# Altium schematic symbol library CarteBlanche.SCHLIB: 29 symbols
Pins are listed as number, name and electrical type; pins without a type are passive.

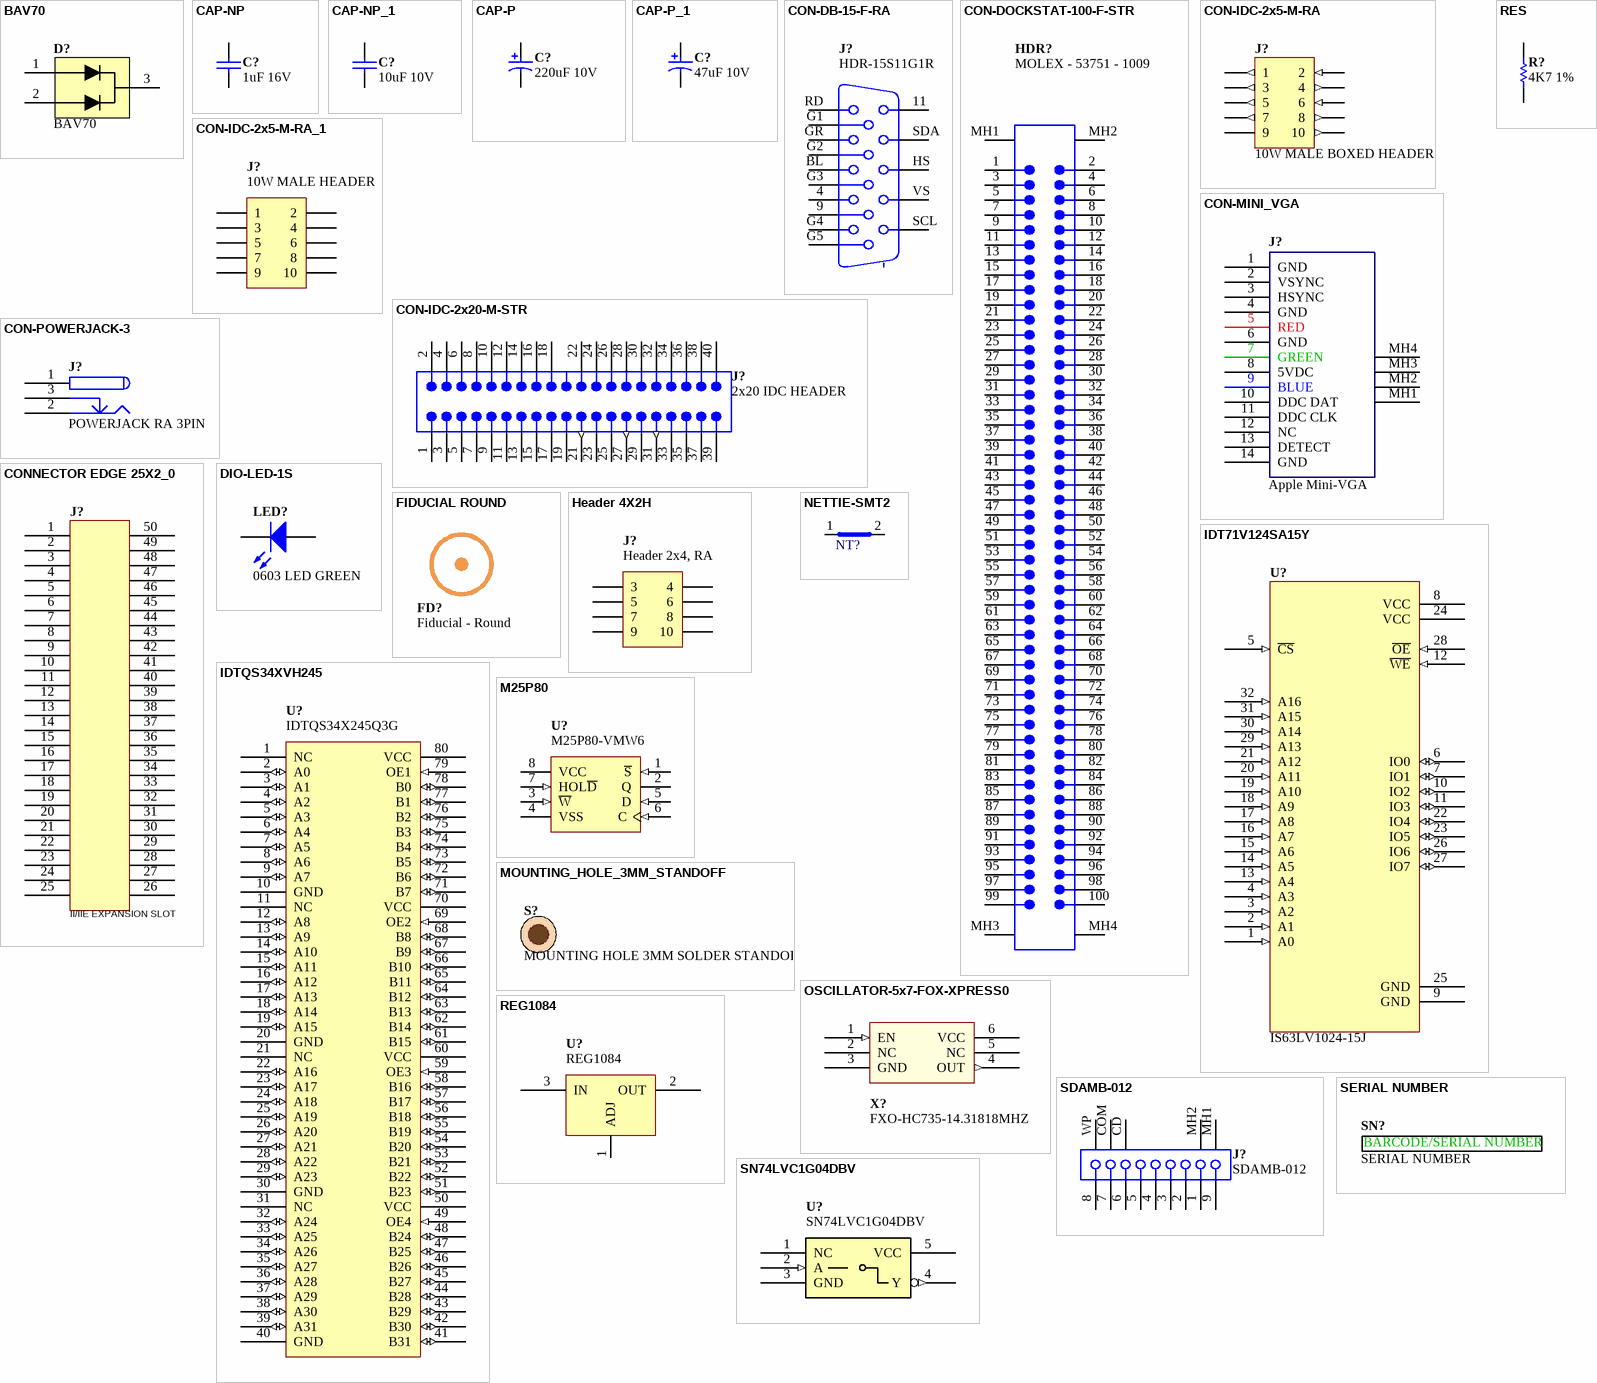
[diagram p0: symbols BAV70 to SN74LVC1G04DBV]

## BAV70
designator D?
BAV70, SOT-23 Shottky Diode Pair Common Cathode
footprint SOT95P230-3
pins: 1, 2, 3
2 alternate drawings of the same symbol

## CAP-NP
designator C?, comment 1uF 16V
Capacitor, Ceramic, 1uF 10% 16V 0402 (1005) X7R
footprint CAPC1005-STAR
pins: 1, 2

## CAP-NP_1
designator C?, comment 10uF 10V
Capacitor, Ceramic, 1uF 10% 16V 0402 (1005) X7R
footprint CAPC1005-STAR
footprint CAPC2012-STAR
pins: 1, 2

## CAP-P
designator C?, comment 220uF 10V
Capacitor, Tantalum, 220uF 10% 10V MCCT-D (7343-31)
footprint CAPC7343-STAR
pins: 1, 2

## CAP-P_1
designator C?, comment 47uF 10V
Capacitor, Tantalum, 220uF 10% 10V MCCT-D (7343-31)
footprint CAPC7343-STAR
footprint CAPC3528-STAR
pins: 1, 2

## CON-DB-15-F-RA
designator J?, comment HDR-15S11G1R
Socket, High-Density DB15 (HD15) Female Through-hole
footprint DB15-VGA-Female
pins: 4 "Monitor ID Bit 2 (Ground)", 9 "Key (not used)", 11 (power) "Monitor ID Bit 0 (Ground)", BL "Blue Video", G1 (power) "Red Return (Ground)", G2 (power) "Green Return (Ground)", G3 (power) "Blue Return (Ground)", G4 (power) "Ground", G5 (power) "Sync Return (Ground)", GR "Green Video", HS "Horizontal Zync", RD "Red Video", SCL "Vertical Sync", SDA "Monitor ID Bit 1 (Not Used)", VS "Vertical Sync"

## CON-DOCKSTAT-100-F-STR
designator HDR?, comment MOLEX - 53751 - 1009
Connector, MOLEX - 53751 - 1009
footprint 53751
pins: 1, 2, 3, 4, 5, 6, 7, 8, 9, 10, 11, 12, 13, 14, 15, 16, 17, 18, 19, 20, 21, 22, 23, 24, 25, 26, 27, 28, 29, 30, 31, 32, 33, 34, 35, 36, 37, 38, 39, 40, 41, 42, 43, 44, 45, 46, 47, 48, 49, 50, 51, 52, 53, 54, 55, 56, 57, 58, 59, 60, 61, 62, 63, 64, 65, 66, 67, 68, 69, 70, 71, 72, 73, 74, 75, 76, 77, 78, 79, 80, 81, 82, 83, 84, 85, 86, 87, 88, 89, 90, 91, 92, 93, 94, 95, 96, 97, 98, 99, 100, MH1, MH2, MH3, MH4
1 alternate drawing of the same symbol

## CON-IDC-2x5-M-RA
designator J?, comment 10W MALE BOXED HEADER
Header IDC, 2x5 Pin Right-Angle 2.54mm Pitch (Boxed-Male)
footprint 918510X323 (Connector; IDC, Low Profile Male Header, Thru-Hole; 10 Position; Right Angle; Pitch 2.54 mm; Body 20.32 x 8.9 x 9.2 mm (LxWxH))
pins: 1 (out), 2 (in), 3 (out), 4 (out), 5 (out), 6 (in), 7 (out), 8 (out), 9, 10 (out)

## CON-IDC-2x5-M-RA_1
designator J?, comment 10W MALE HEADER
Header IDC, 2x5 Pin Right-Angle 2.54mm Pitch (Boxed-Male)
footprint 918510X323 (Connector; IDC, Low Profile Male Header, Thru-Hole; 10 Position; Right Angle; Pitch 2.54 mm; Body 20.32 x 8.9 x 9.2 mm (LxWxH))
pins: 1, 2, 3, 4, 5, 6, 7, 8, 9, 10

## CON-IDC-2x20-M-STR
designator J?, comment 2x20 IDC HEADER
Header, Boxed 2x20 Pin Vertical 2.54mm Pitch
footprint 918540x324
pins: 1, 2, 3, 4, 5, 6, 7, 8, 9, 10, 11, 12, 13, 14, 15, 16, 17, 18, 19, 21 (out), 22, 23, 24, 25, 26, 27 (out), 28, 29, 30, 31 (out), 32, 33, 34, 35, 36, 37, 38, 39, 40

## CON-MINI_VGA
designator J?, comment Apple Mini-VGA  (no BOM)
Socket, VGA/RGB Connector, 1.00mm Pitch, Through-hole, Suyin
footprint CON_MINI_VGA
pins: 1 GND, 2 VSYNC, 3 HSYNC, 4 GND, 5 RED, 6 GND, 7 GREEN, 8 5VDC, 9 BLUE, 10 DDC DAT, 11 DDC CLK, 12 NC, 13 DETECT, 14 GND, MH1, MH2, MH3, MH4

## CON-POWERJACK-3
designator J?, comment POWERJACK RA 3PIN
Connector, RA 3 Conductor Power Jack
footprint KLD-0202
pins: 1 (power), 2 (power), 3 (power)

## CONNECTOR EDGE 25X2_0
designator J?, comment II/IIE EXPANSION SLOT  (no BOM)
footprint APPLE II EDGE CONNECTOR (Footprint not found)
pins: 1, 2, 3, 4, 5, 6, 7, 8, 9, 10, 11, 12, 13, 14, 15, 16, 17, 18, 19, 20, 21, 22, 23, 24, 25, 26, 27, 28, 29, 30, 31, 32, 33, 34, 35, 36, 37, 38, 39, 40, 41, 42, 43, 44, 45, 46, 47, 48, 49, 50

## DIO-LED-1S
designator LED?, comment 0603 LED GREEN
LED, SMD Green 0603 (1608) 60mCd
footprint 0603LED_Kingbright_Green
pins: 1 A, 2 K

## FIDUCIAL ROUND
designator FD?, comment Fiducial - Round
Fiducial - Round 1.5mm Top-Bottom
footprint FIDUCIAL ROUND

## Header 4X2H
designator J?, comment Header 2x4, RA
Header, Right Angle, 8-Pin, Dual row
footprint HDR2X4H (Connector; Header; 4x2 Position; Right Angle)
pins: 3, 4, 5, 6, 7, 8, 9, 10

## IDT71V124SA15Y
designator U?, comment IS63LV1024-15J
IC SRAM 128Kx8 15nS ASYNC 32-SOJ
footprint SO-J32
pins: 1 A0 (in) "Address 0", 2 A1 (in) "Address 1", 3 A2 (in) "Address 3", 4 A3 (in) "Address 3", 5 ~{CS} (in) "Chip Select", 6 IO0 (io) "Data 0", 7 IO1 (io) "Data 1", 8 VCC (power) "Pos Supply", 9 GND (power), 10 IO2 (io) "Data 2", 11 IO3 (io) "Data 3", 12 ~{WE} (in) "Write Enable", 13 A4 (in) "Address 4", 14 A5 (in) "Address 5", 15 A6 (in) "Address 6", 16 A7 (in) "Address 7", 17 A8 (in) "Address 8", 18 A9 (in) "Address 9", 19 A10 (in) "Address 10", 20 A11 (in) "Address 11", 21 A12 (in) "Address 12", 22 IO4 (io) "Data 4", 23 IO5 (io) "Data 5", 24 VCC (power) "Pos Supply", 25 GND (power), 26 IO6 (io) "Data 6", 27 IO7 (io) "Data 7", 28 ~{OE} (in) "Output Enable", 29 A13 (in) "Address 13", 30 A14 (in) "Address 14", 31 A15 (in) "Address 15", 32 A16 (in) "Address 16"

## IDTQS34XVH245
designator U?, comment IDTQS34X245Q3G
IC BUS SWITCH 32BIT CMOS 80QVSOP
footprint QVSOP80 (Footprint not found)
pins: 1 NC "Analog Input 0", 2 A0 (io) "Analog Input 0", 3 A1 (io) "Analog Input 0", 4 A2 (io) "Analog Input 3/ Reference Input", 5 A3 (io) "I2C Clock Line", 6 A4 (io) "I2C Data Line", 7 A5 (io) "GND", 8 A6 (io), 9 A7 (io), 10 GND (power), 11 NC, 12 A8 (io), 13 A9 (io), 14 A10 (io), 15 A11 (io), 16 A12 (io), 17 A13 (io), 18 A14 (io), 19 A15 (io), 20 GND (power), 21 NC, 22 A16 (io), 23 A17 (io), 24 A18 (io), 25 A19 (io), 26 A20 (io), 27 A21 (io), 28 A22 (io), 29 A23 (io), 30 GND (power), 31 NC, 32 A24 (io), 33 A25 (io), 34 A26 (io), 35 A27 (io), 36 A28 (io), 37 A29 (io), 38 A30 (io), 39 A31 (io), 40 GND (power), 41 B31 (io), 42 B30 (io), 43 B29 (io), 44 B28 (io), 45 B27 (io), 46 B26 (io), 47 B25 (io), 48 B24 (io), 49 OE4 (in), 50 VCC (power), 51 B23 (io), 52 B22 (io), 53 B21 (io), 54 B20 (io), 55 B19 (io), 56 B18 (io), 57 B17 (io), 58 B16 (io), 59 OE3 (in), 60 VCC (power), 61 B15 (io), 62 B14 (io), 63 B13 (io), 64 B12 (io), 65 B11 (io), 66 B10 (io), 67 B9 (io), 68 B8 (io), 69 OE2 (in), 70 VCC (power), 71 B7 (io), 72 B6 (io), 73 B5 (io), 74 B4 (io), 75 B3 (io), 76 B2 (io), 77 B1 (io), 78 B0 (io), 79 OE1 (in), 80 VCC (power)

## M25P80
designator U?, comment M25P80-VMW6
IC SERIAL FLASH 8MBIT 3V 8-SOIC WIDE
footprint SOIC8-200-BODY
pins: 1 ~{S} (in), 2 Q (hiz) "Serial Output", 3 ~{W} (in) "Serial Output", 4 VSS (power) "Serial Output", 5 D (in) "Serial Input", 6 C (in) "Serial Input", 7 HOL~{D} (in) "Serial Input", 8 VCC (power) "Serial Input"

## MOUNTING_HOLE_3MM_STANDOFF
designator S?, comment MOUNTING HOLE 3MM SOLDER STANDOFF
Solder Standoff, M3 Screw, Gold Plated, Round Pad
footprint STANDOFF_SOLDER_3MM
pins: 1 hidden

## NETTIE-SMT2
designator NT?, comment Net Tie SMT2  (value not drawn)  (net tie, no BOM)
Net-Tie, Surface Mount, 2 x 0.4mm x 0.2mm SMT Pads - For 0.2mm Track
footprint NETTIE-SMT2-31X51 (Footprint not found)
pins: 1 Net1, 2 Net2

## OSCILLATOR-5x7-FOX-XPRESS0
designator X?, comment FXO-HC735-14.31818MHZ
OSCILLATOR 14.31818 MHZ 3.3V SMD
footprint OSCILLATOR-5x7-FOX-XPRESS0
pins: 1 EN (in), 2 NC, 3 GND (power), 4 OUT (out), 5 NC, 6 VCC (power)

## REG1084
designator U?
IC REG POSITIVE 5A LDO TO-263
footprint TO-263
pins: 1 ADJ, 2 OUT, 3 IN

## RES
designator R?, comment 4K7 1%
Resistor, 4K7 1% 0402 (1005)
footprint RESC1005-STAR
pins: 1, 2

## SDAMB-012
designator J?
KINGFONT SDCARD Connector SDAMB-012
footprint SDAMB-012
pins: 1 "CD/DAT3", 2 "CMD/D1", 3 "VSS1", 4 "VDD", 5 "CLK/SCLK", 6 "VSS2", 7 "DAT0", 8 "DAT1", 9 "DAT3", CD "Card Detect Indication", COM, MH1 "Tab", MH2 "Tab", WP "Write Protect"

## SERIAL NUMBER
designator SN?  (no BOM)
footprint SERIAL_NO2 (Footprint not found)

## SN74LVC1G04DBV
designator U?
IC SINGLE INVERTER-GATE SOT-23-5
footprint SOT95P280-5
pins: 1 NC, 2 A (in), 3 GND (power), 4 Y (out), 5 VCC (power)

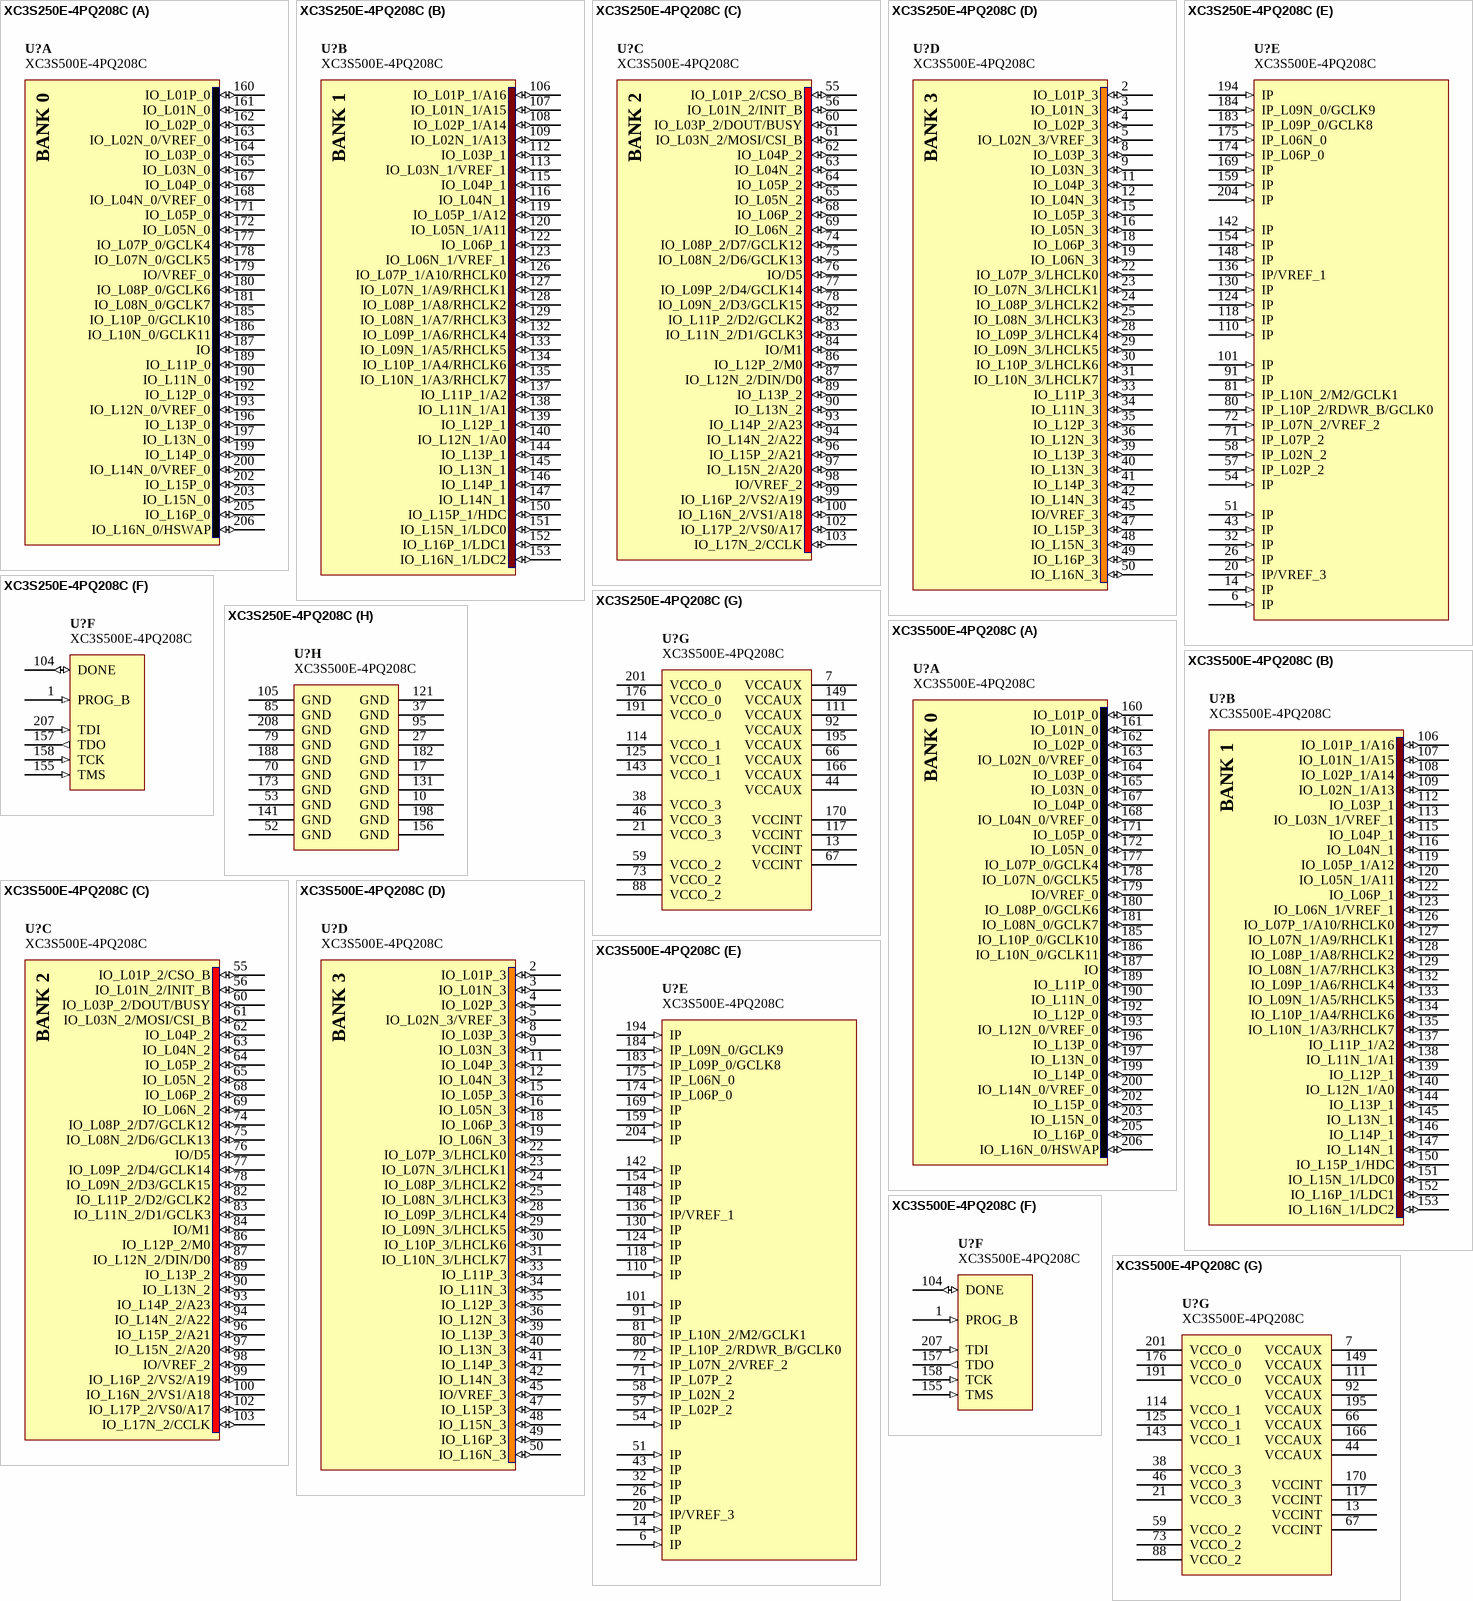
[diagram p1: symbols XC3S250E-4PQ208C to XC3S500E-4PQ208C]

## XC3S250E-4PQ208C
designator U?, comment XC3S500E-4PQ208C
IC SPARTAN-3E FPGA 500K 208-PQFP; EnablePinSwap: True
footprint PQ208_N (Shrink QFP, 208-Leads, Body 28x28mm, Pitch 0.5mm, IPC Medium Density)
footprint PQ208_L (Shrink QFP, 208-Leads, Body 28x28mm, Pitch 0.5mm, IPC High Density)
footprint PQ208_M (Shrink QFP, 208-Leads, Body 28x28mm, Pitch 0.5mm, IPC Low Density)
3D model XC3S250E-PQ208 (208-Pin Plastic Quad Flat Pack (PQ208))
signal-integrity model XC3S250E_PQ208 (Spartan-3E)
part A pins: 160 IO_L01P_0 (io), 161 IO_L01N_0 (io), 162 IO_L02P_0 (io), 163 IO_L02N_0/VREF_0 (io), 164 IO_L03P_0 (io), 165 IO_L03N_0 (io), 167 IO_L04P_0 (io), 168 IO_L04N_0/VREF_0 (io), 171 IO_L05P_0 (io), 172 IO_L05N_0 (io), 177 IO_L07P_0/GCLK4 (io), 178 IO_L07N_0/GCLK5 (io), 179 IO/VREF_0 (io), 180 IO_L08P_0/GCLK6 (io), 181 IO_L08N_0/GCLK7 (io), 185 IO_L10P_0/GCLK10 (io), 186 IO_L10N_0/GCLK11 (io), 187 IO (io), 189 IO_L11P_0 (io), 190 IO_L11N_0 (io), 192 IO_L12P_0 (io), 193 IO_L12N_0/VREF_0 (io), 196 IO_L13P_0 (io), 197 IO_L13N_0 (io), 199 IO_L14P_0 (io), 200 IO_L14N_0/VREF_0 (io), 202 IO_L15P_0 (io), 203 IO_L15N_0 (io), 205 IO_L16P_0 (io), 206 IO_L16N_0/HSWAP (io)
part B pins: 106 IO_L01P_1/A16 (io), 107 IO_L01N_1/A15 (io), 108 IO_L02P_1/A14 (io), 109 IO_L02N_1/A13 (io), 112 IO_L03P_1 (io), 113 IO_L03N_1/VREF_1 (io), 115 IO_L04P_1 (io), 116 IO_L04N_1 (io), 119 IO_L05P_1/A12 (io), 120 IO_L05N_1/A11 (io), 122 IO_L06P_1 (io), 123 IO_L06N_1/VREF_1 (io), 126 IO_L07P_1/A10/RHCLK0 (io), 127 IO_L07N_1/A9/RHCLK1 (io), 128 IO_L08P_1/A8/RHCLK2 (io), 129 IO_L08N_1/A7/RHCLK3 (io), 132 IO_L09P_1/A6/RHCLK4 (io), 133 IO_L09N_1/A5/RHCLK5 (io), 134 IO_L10P_1/A4/RHCLK6 (io), 135 IO_L10N_1/A3/RHCLK7 (io), 137 IO_L11P_1/A2 (io), 138 IO_L11N_1/A1 (io), 139 IO_L12P_1 (io), 140 IO_L12N_1/A0 (io), 144 IO_L13P_1 (io), 145 IO_L13N_1 (io), 146 IO_L14P_1 (io), 147 IO_L14N_1 (io), 150 IO_L15P_1/HDC (io), 151 IO_L15N_1/LDC0 (io), 152 IO_L16P_1/LDC1 (io), 153 IO_L16N_1/LDC2 (io)
part C pins: 55 IO_L01P_2/CSO_B (io), 56 IO_L01N_2/INIT_B (io), 60 IO_L03P_2/DOUT/BUSY (io), 61 IO_L03N_2/MOSI/CSI_B (io), 62 IO_L04P_2 (io), 63 IO_L04N_2 (io), 64 IO_L05P_2 (io), 65 IO_L05N_2 (io), 68 IO_L06P_2 (io), 69 IO_L06N_2 (io), 74 IO_L08P_2/D7/GCLK12 (io), 75 IO_L08N_2/D6/GCLK13 (io), 76 IO/D5 (io), 77 IO_L09P_2/D4/GCLK14 (io), 78 IO_L09N_2/D3/GCLK15 (io), 82 IO_L11P_2/D2/GCLK2 (io), 83 IO_L11N_2/D1/GCLK3 (io), 84 IO/M1 (io), 86 IO_L12P_2/M0 (io), 87 IO_L12N_2/DIN/D0 (io), 89 IO_L13P_2 (io), 90 IO_L13N_2 (io), 93 IO_L14P_2/A23 (io), 94 IO_L14N_2/A22 (io), 96 IO_L15P_2/A21 (io), 97 IO_L15N_2/A20 (io), 98 IO/VREF_2 (io), 99 IO_L16P_2/VS2/A19 (io), 100 IO_L16N_2/VS1/A18 (io), 102 IO_L17P_2/VS0/A17 (io), 103 IO_L17N_2/CCLK (io)
part D pins: 2 IO_L01P_3 (io), 3 IO_L01N_3 (io), 4 IO_L02P_3 (io), 5 IO_L02N_3/VREF_3 (io), 8 IO_L03P_3 (io), 9 IO_L03N_3 (io), 11 IO_L04P_3 (io), 12 IO_L04N_3 (io), 15 IO_L05P_3 (io), 16 IO_L05N_3 (io), 18 IO_L06P_3 (io), 19 IO_L06N_3 (io), 22 IO_L07P_3/LHCLK0 (io), 23 IO_L07N_3/LHCLK1 (io), 24 IO_L08P_3/LHCLK2 (io), 25 IO_L08N_3/LHCLK3 (io), 28 IO_L09P_3/LHCLK4 (io), 29 IO_L09N_3/LHCLK5 (io), 30 IO_L10P_3/LHCLK6 (io), 31 IO_L10N_3/LHCLK7 (io), 33 IO_L11P_3 (io), 34 IO_L11N_3 (io), 35 IO_L12P_3 (io), 36 IO_L12N_3 (io), 39 IO_L13P_3 (io), 40 IO_L13N_3 (io), 41 IO_L14P_3 (io), 42 IO_L14N_3 (io), 45 IO/VREF_3 (io), 47 IO_L15P_3 (io), 48 IO_L15N_3 (io), 49 IO_L16P_3 (io), 50 IO_L16N_3 (io)
part E pins: 6 IP (in), 14 IP (in), 20 IP/VREF_3 (in), 26 IP (in), 32 IP (in), 43 IP (in), 51 IP (in), 54 IP (in), 57 IP_L02P_2 (in), 58 IP_L02N_2 (in), 71 IP_L07P_2 (in), 72 IP_L07N_2/VREF_2 (in), 80 IP_L10P_2/RDWR_B/GCLK0 (in), 81 IP_L10N_2/M2/GCLK1 (in), 91 IP (in), 101 IP (in), 110 IP (in), 118 IP (in), 124 IP (in), 130 IP (in), 136 IP/VREF_1 (in), 142 IP (in), 148 IP (in), 154 IP (in), 159 IP (in), 169 IP (in), 174 IP_L06P_0 (in), 175 IP_L06N_0 (in), 183 IP_L09P_0/GCLK8 (in), 184 IP_L09N_0/GCLK9 (in), 194 IP (in), 204 IP (in)
part F pins: 1 PROG_B (in), 104 DONE (io), 155 TMS (in), 157 TDO (out), 158 TCK (in), 207 TDI (in)
part G pins: 7 VCCAUX (power), 13 VCCINT (power), 21 VCCO_3 (power), 38 VCCO_3 (power), 44 VCCAUX (power), 46 VCCO_3 (power), 59 VCCO_2 (power), 66 VCCAUX (power), 67 VCCINT (power), 73 VCCO_2 (power), 88 VCCO_2 (power), 92 VCCAUX (power), 111 VCCAUX (power), 114 VCCO_1 (power), 117 VCCINT (power), 125 VCCO_1 (power), 143 VCCO_1 (power), 149 VCCAUX (power), 166 VCCAUX (power), 170 VCCINT (power), 176 VCCO_0 (power), 191 VCCO_0 (power), 195 VCCAUX (power), 201 VCCO_0 (power)
part H pins: 10 GND (power), 17 GND (power), 27 GND (power), 37 GND (power), 52 GND (power), 53 GND (power), 70 GND (power), 79 GND (power), 85 GND (power), 95 GND (power), 105 GND (power), 121 GND (power), 131 GND (power), 141 GND (power), 156 GND (power), 173 GND (power), 182 GND (power), 188 GND (power), 198 GND (power), 208 GND (power)

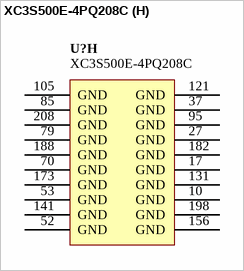
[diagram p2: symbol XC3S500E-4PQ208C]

## XC3S500E-4PQ208C
designator U?
IC SPARTAN-3E FPGA 500K 208-PQFP; EnablePinSwap: True
footprint PQ208_N (Shrink QFP, 208-Leads, Body 28x28mm, Pitch 0.5mm, IPC Medium Density)
footprint PQ208_L (Shrink QFP, 208-Leads, Body 28x28mm, Pitch 0.5mm, IPC High Density)
footprint PQ208_M (Shrink QFP, 208-Leads, Body 28x28mm, Pitch 0.5mm, IPC Low Density)
3D model XC3S500E-PQ208 (208-Pin Plastic Quad Flat Pack (PQ208))
signal-integrity model XC3S500E_PQ208 (Spartan-3E)
part A pins: 160 IO_L01P_0 (io), 161 IO_L01N_0 (io), 162 IO_L02P_0 (io), 163 IO_L02N_0/VREF_0 (io), 164 IO_L03P_0 (io), 165 IO_L03N_0 (io), 167 IO_L04P_0 (io), 168 IO_L04N_0/VREF_0 (io), 171 IO_L05P_0 (io), 172 IO_L05N_0 (io), 177 IO_L07P_0/GCLK4 (io), 178 IO_L07N_0/GCLK5 (io), 179 IO/VREF_0 (io), 180 IO_L08P_0/GCLK6 (io), 181 IO_L08N_0/GCLK7 (io), 185 IO_L10P_0/GCLK10 (io), 186 IO_L10N_0/GCLK11 (io), 187 IO (io), 189 IO_L11P_0 (io), 190 IO_L11N_0 (io), 192 IO_L12P_0 (io), 193 IO_L12N_0/VREF_0 (io), 196 IO_L13P_0 (io), 197 IO_L13N_0 (io), 199 IO_L14P_0 (io), 200 IO_L14N_0/VREF_0 (io), 202 IO_L15P_0 (io), 203 IO_L15N_0 (io), 205 IO_L16P_0 (io), 206 IO_L16N_0/HSWAP (io)
part B pins: 106 IO_L01P_1/A16 (io), 107 IO_L01N_1/A15 (io), 108 IO_L02P_1/A14 (io), 109 IO_L02N_1/A13 (io), 112 IO_L03P_1 (io), 113 IO_L03N_1/VREF_1 (io), 115 IO_L04P_1 (io), 116 IO_L04N_1 (io), 119 IO_L05P_1/A12 (io), 120 IO_L05N_1/A11 (io), 122 IO_L06P_1 (io), 123 IO_L06N_1/VREF_1 (io), 126 IO_L07P_1/A10/RHCLK0 (io), 127 IO_L07N_1/A9/RHCLK1 (io), 128 IO_L08P_1/A8/RHCLK2 (io), 129 IO_L08N_1/A7/RHCLK3 (io), 132 IO_L09P_1/A6/RHCLK4 (io), 133 IO_L09N_1/A5/RHCLK5 (io), 134 IO_L10P_1/A4/RHCLK6 (io), 135 IO_L10N_1/A3/RHCLK7 (io), 137 IO_L11P_1/A2 (io), 138 IO_L11N_1/A1 (io), 139 IO_L12P_1 (io), 140 IO_L12N_1/A0 (io), 144 IO_L13P_1 (io), 145 IO_L13N_1 (io), 146 IO_L14P_1 (io), 147 IO_L14N_1 (io), 150 IO_L15P_1/HDC (io), 151 IO_L15N_1/LDC0 (io), 152 IO_L16P_1/LDC1 (io), 153 IO_L16N_1/LDC2 (io)
part C pins: 55 IO_L01P_2/CSO_B (io), 56 IO_L01N_2/INIT_B (io), 60 IO_L03P_2/DOUT/BUSY (io), 61 IO_L03N_2/MOSI/CSI_B (io), 62 IO_L04P_2 (io), 63 IO_L04N_2 (io), 64 IO_L05P_2 (io), 65 IO_L05N_2 (io), 68 IO_L06P_2 (io), 69 IO_L06N_2 (io), 74 IO_L08P_2/D7/GCLK12 (io), 75 IO_L08N_2/D6/GCLK13 (io), 76 IO/D5 (io), 77 IO_L09P_2/D4/GCLK14 (io), 78 IO_L09N_2/D3/GCLK15 (io), 82 IO_L11P_2/D2/GCLK2 (io), 83 IO_L11N_2/D1/GCLK3 (io), 84 IO/M1 (io), 86 IO_L12P_2/M0 (io), 87 IO_L12N_2/DIN/D0 (io), 89 IO_L13P_2 (io), 90 IO_L13N_2 (io), 93 IO_L14P_2/A23 (io), 94 IO_L14N_2/A22 (io), 96 IO_L15P_2/A21 (io), 97 IO_L15N_2/A20 (io), 98 IO/VREF_2 (io), 99 IO_L16P_2/VS2/A19 (io), 100 IO_L16N_2/VS1/A18 (io), 102 IO_L17P_2/VS0/A17 (io), 103 IO_L17N_2/CCLK (io)
part D pins: 2 IO_L01P_3 (io), 3 IO_L01N_3 (io), 4 IO_L02P_3 (io), 5 IO_L02N_3/VREF_3 (io), 8 IO_L03P_3 (io), 9 IO_L03N_3 (io), 11 IO_L04P_3 (io), 12 IO_L04N_3 (io), 15 IO_L05P_3 (io), 16 IO_L05N_3 (io), 18 IO_L06P_3 (io), 19 IO_L06N_3 (io), 22 IO_L07P_3/LHCLK0 (io), 23 IO_L07N_3/LHCLK1 (io), 24 IO_L08P_3/LHCLK2 (io), 25 IO_L08N_3/LHCLK3 (io), 28 IO_L09P_3/LHCLK4 (io), 29 IO_L09N_3/LHCLK5 (io), 30 IO_L10P_3/LHCLK6 (io), 31 IO_L10N_3/LHCLK7 (io), 33 IO_L11P_3 (io), 34 IO_L11N_3 (io), 35 IO_L12P_3 (io), 36 IO_L12N_3 (io), 39 IO_L13P_3 (io), 40 IO_L13N_3 (io), 41 IO_L14P_3 (io), 42 IO_L14N_3 (io), 45 IO/VREF_3 (io), 47 IO_L15P_3 (io), 48 IO_L15N_3 (io), 49 IO_L16P_3 (io), 50 IO_L16N_3 (io)
part E pins: 6 IP (in), 14 IP (in), 20 IP/VREF_3 (in), 26 IP (in), 32 IP (in), 43 IP (in), 51 IP (in), 54 IP (in), 57 IP_L02P_2 (in), 58 IP_L02N_2 (in), 71 IP_L07P_2 (in), 72 IP_L07N_2/VREF_2 (in), 80 IP_L10P_2/RDWR_B/GCLK0 (in), 81 IP_L10N_2/M2/GCLK1 (in), 91 IP (in), 101 IP (in), 110 IP (in), 118 IP (in), 124 IP (in), 130 IP (in), 136 IP/VREF_1 (in), 142 IP (in), 148 IP (in), 154 IP (in), 159 IP (in), 169 IP (in), 174 IP_L06P_0 (in), 175 IP_L06N_0 (in), 183 IP_L09P_0/GCLK8 (in), 184 IP_L09N_0/GCLK9 (in), 194 IP (in), 204 IP (in)
part F pins: 1 PROG_B (in), 104 DONE (io), 155 TMS (in), 157 TDO (out), 158 TCK (in), 207 TDI (in)
part G pins: 7 VCCAUX (power), 13 VCCINT (power), 21 VCCO_3 (power), 38 VCCO_3 (power), 44 VCCAUX (power), 46 VCCO_3 (power), 59 VCCO_2 (power), 66 VCCAUX (power), 67 VCCINT (power), 73 VCCO_2 (power), 88 VCCO_2 (power), 92 VCCAUX (power), 111 VCCAUX (power), 114 VCCO_1 (power), 117 VCCINT (power), 125 VCCO_1 (power), 143 VCCO_1 (power), 149 VCCAUX (power), 166 VCCAUX (power), 170 VCCINT (power), 176 VCCO_0 (power), 191 VCCO_0 (power), 195 VCCAUX (power), 201 VCCO_0 (power)
part H pins: 10 GND (power), 17 GND (power), 27 GND (power), 37 GND (power), 52 GND (power), 53 GND (power), 70 GND (power), 79 GND (power), 85 GND (power), 95 GND (power), 105 GND (power), 121 GND (power), 131 GND (power), 141 GND (power), 156 GND (power), 173 GND (power), 182 GND (power), 188 GND (power), 198 GND (power), 208 GND (power)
